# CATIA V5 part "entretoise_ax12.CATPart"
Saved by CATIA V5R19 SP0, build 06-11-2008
Part number: entretoise_ax12
Bounding box of the stored display mesh (mm): x 0 to 2, y -5.75 to 5.75, z -5.749 to 5.749
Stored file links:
  C:\Users\Rémi\Documents\BTS CPI\Projet 04- Guitar Elec\Maquette 3D\Moteur\entretoise_ax12.CATPart
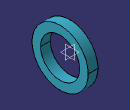
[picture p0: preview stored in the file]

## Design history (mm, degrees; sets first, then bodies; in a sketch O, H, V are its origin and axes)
Body1 (main body)
  Sketch1 on yz-plane, origin (0, 0, 0), H (0, 1, 0), V (0, 0, 1)
    circle A1 centre (0, 0) radius 4
    circle A2 centre (0, 0) radius 5.75
    radius A1 = 4
    radius A2 = 5.75
  Pad1: profile Sketch1, direction (1, 0, 0), length 2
